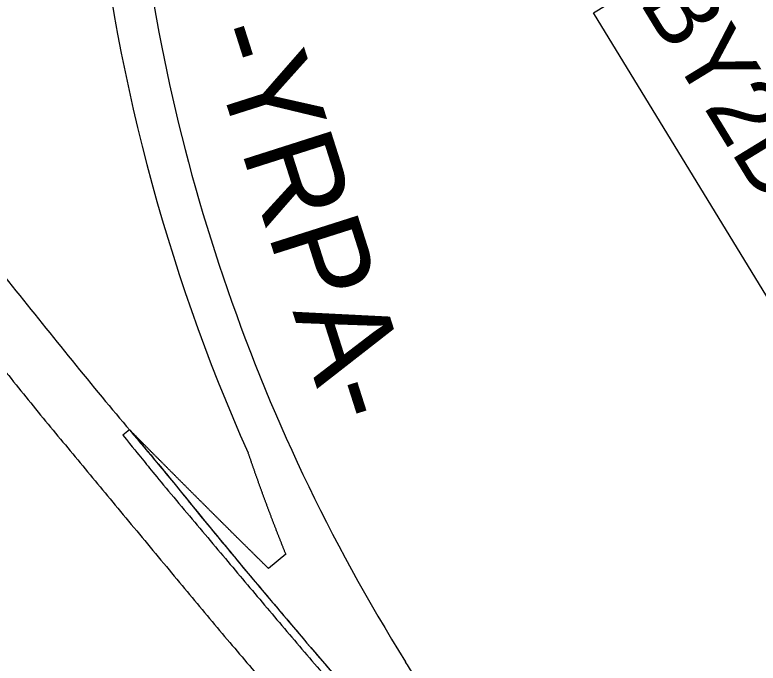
# Model space of a CAD drawing. Extents: x 1771071 to 1790027, y 804210 to 823391.
# Drawn here: x 1782402.5 to 1782802.4, y 812654.6 to 813003.3 of the extents above; entities that cross this region are included whole.
import ezdxf

# ---------------------------------------------------------------- set-up
doc = ezdxf.new("R2010")
doc.units = 0
for name, color, linetype in [('Default', 7, 'Continuous'), ('Exist Roads EOP', 7, 'Continuous'), ('Proposed Right of Way Monument PSD Text', 7, 'Continuous'), ('Scratch_Level_1', 7, 'Continuous'), ('Scratch_Level_7', 7, 'Continuous'), ('Scratch_Level_8', 7, 'Continuous')]:
    doc.layers.add(name, color=color, linetype=linetype)

msp = doc.modelspace()

# ---------------------------------------------------------------- linework, layer by layer
at = {"layer": 'Default'}
msp.add_lwpolyline([(1782786, 813048.4), (1782912.68, 812841.06), (1782840.57, 812797), (1782713.88, 813004.34)], close=True, dxfattribs=at)
at = {"layer": 'Exist Roads EOP'}
msp.add_spline([(1781123.7, 814794.56), (1781151.95, 814749.7), (1781175.35, 814711.94), (1781204.02, 814667.22), (1781230.05, 814626.42), (1781255.51, 814585.11), (1781282.93, 814541.39), (1781309.04, 814500.81), (1781338.07, 814453.82), (1781362.44, 814415.66), (1781389.1, 814373.22), (1781417.2, 814328.4), (1781443.82, 814286), (1781469.22, 814245.27), (1781496.33, 814201.88), (1781523.28, 814159.28), (1781551.49, 814114.9), (1781575, 814076.8), (1781602.27, 814034.47), (1781628.68, 813992.42), (1781657.71, 813946.44), (1781682.97, 813906.24), (1781710.54, 813862.11), (1781734.73, 813823.58), (1781763.09, 813779.24), (1781788.41, 813738.38), (1781814.81, 813696.35), (1781842.37, 813653.36), (1781868.91, 813610.68), (1781895.83, 813568.71), (1781924.39, 813523.58), (1781950.61, 813481.8), (1781976.68, 813442.67), (1782004.37, 813401.37), (1782031.99, 813360.12), (1782060.77, 813317.53), (1782089.19, 813276.64), (1782119.2, 813233.31), (1782146.2, 813195.67), (1782175.13, 813155.14), (1782204.07, 813115.4), (1782233.24, 813075.72), (1782263.79, 813034.43), (1782294.03, 812994.29), (1782325.04, 812953.86), (1782354.41, 812916.21), (1782385, 812877.38), (1782417.21, 812837.26), (1782449.43, 812797.65), (1782479.54, 812761.76), (1782513.17, 812720.66), (1782543.05, 812684.98), (1782576.35, 812645.89), (1782608.48, 812608.74), (1782640.69, 812571.37), (1782677.39, 812530.96), (1782710.34, 812494.65), (1782741.2, 812460.83), (1782775.54, 812424.09), (1782810.15, 812387.02), (1782844.36, 812350.73), (1782880.69, 812313.19), (1782914.85, 812277.64), (1782949.87, 812242.16), (1782985.13, 812206.92), (1783022.44, 812170.42), (1783054.86, 812138.57), (1783094.75, 812100.54), (1783130.02, 812066.91), (1783162.74, 812036.24), (1783200.85, 812001.49), (1783239.6, 811965.96), (1783275.52, 811933.35), (1783312.46, 811900.79)], degree=3, dxfattribs=at)
msp.add_open_spline([(1782044.92, 813285.25), (1782050.67, 813276.97), (1782056.46, 813268.71), (1782062.24, 813260.44), (1782072.54, 813245.71), (1782082.87, 813230.99), (1782093.24, 813216.29), (1782102.63, 813202.96), (1782112.08, 813189.67), (1782121.53, 813176.38), (1782130.68, 813163.53), (1782139.84, 813150.7), (1782149.05, 813137.9), (1782158.82, 813124.32), (1782168.64, 813110.78), (1782178.47, 813097.24), (1782188.39, 813083.57), (1782198.35, 813069.92), (1782208.33, 813056.29), (1782218.02, 813043.06), (1782227.8, 813029.89), (1782237.65, 813016.78), (1782248.53, 813002.3), (1782259.48, 812987.88), (1782270.47, 812973.49), (1782279.84, 812961.23), (1782289.23, 812948.99), (1782298.65, 812936.76), (1782309.31, 812922.92), (1782320.02, 812909.11), (1782330.76, 812895.33), (1782340.48, 812882.84), (1782350.26, 812870.4), (1782360.1, 812858.01), (1782370.44, 812844.98), (1782380.85, 812832.02), (1782391.28, 812819.08), (1782401.82, 812806), (1782412.32, 812792.9), (1782423.02, 812779.96), (1782433.65, 812767.11), (1782444.31, 812754.28), (1782454.97, 812741.45), (1782466.58, 812727.47), (1782478.2, 812713.49), (1782489.81, 812699.52), (1782500.55, 812686.61), (1782511.28, 812673.7), (1782522.16, 812660.91), (1782532.57, 812648.66), (1782543.09, 812636.51), (1782553.61, 812624.36), (1782564.93, 812611.27), (1782576.27, 812598.2), (1782587.59, 812585.12), (1782598.39, 812572.65), (1782609.08, 812560.09), (1782619.9, 812547.64), (1782629.97, 812536.06), (1782640.33, 812524.75), (1782650.68, 812513.41), (1782662.01, 812501), (1782673.39, 812488.63), (1782684.72, 812476.21), (1782696.75, 812463.02), (1782708.67, 812449.73), (1782720.73, 812436.57), (1782731.28, 812425.06), (1782741.93, 812413.64), (1782752.57, 812402.22), (1782763.95, 812390), (1782775.33, 812377.78), (1782786.79, 812365.63), (1782798.36, 812353.36), (1782809.99, 812341.16), (1782821.65, 812328.98), (1782834.08, 812316), (1782846.53, 812303.03), (1782859, 812290.07), (1782870.02, 812278.6), (1782880.99, 812267.09), (1782892.16, 812255.75), (1782903.38, 812244.37), (1782914.67, 812233.06), (1782925.94, 812221.72), (1782937.72, 812209.87), (1782949.5, 812198.01), (1782961.31, 812186.19), (1782973.07, 812174.42), (1782984.95, 812162.79), (1782996.81, 812151.13), (1783009.36, 812138.79), (1783021.93, 812126.45), (1783034.55, 812114.18), (1783046.41, 812102.66), (1783058.37, 812091.23), (1783070.34, 812079.83), (1783082.49, 812068.26), (1783094.66, 812056.71), (1783106.9, 812045.24), (1783119.62, 812033.34), (1783132.37, 812021.48), (1783145.13, 812009.62), (1783156.44, 811999.11), (1783167.76, 811988.6), (1783179.13, 811978.15), (1783191.42, 811966.86), (1783203.78, 811955.65), (1783216.13, 811944.44), (1783228.56, 811933.16), (1783241, 811921.89), (1783253.48, 811910.66), (1783266.09, 811899.3), (1783278.79, 811888.04), (1783291.5, 811876.8), (1783304.26, 811865.51), (1783317.04, 811854.25), (1783329.93, 811843.12), (1783341.92, 811832.75), (1783353.96, 811822.43), (1783366.03, 811812.15), (1783379.44, 811800.73), (1783392.86, 811789.32), (1783406.3, 811777.93), (1783419.39, 811766.84), (1783432.5, 811755.79), (1783445.62, 811744.73), (1783457.8, 811734.47), (1783469.97, 811724.21), (1783482.3, 811714.13), (1783494.7, 811704.01), (1783507.23, 811694.06), (1783519.67, 811683.97), (1783533.96, 811672.38), (1783548.22, 811660.73), (1783562.53, 811649.15), (1783574.14, 811639.75), (1783585.77, 811630.37), (1783597.48, 811621.1), (1783597.98, 811620.7), (1783598.49, 811620.3), (1783598.99, 811619.91)], degree=3, dxfattribs=at)
at = {"layer": 'Scratch_Level_1'}
msp.add_open_spline([(1782464.13, 812780.09), (1782469.29, 812774), (1782474.45, 812767.91), (1782479.54, 812761.76), (1782490.82, 812748.12), (1782501.87, 812734.28), (1782513.17, 812720.66), (1782523.08, 812708.72), (1782533.03, 812696.82), (1782543.05, 812684.98), (1782554.11, 812671.91), (1782565.17, 812658.85), (1782576.35, 812645.89), (1782587.05, 812633.5), (1782597.78, 812621.13), (1782608.48, 812608.74), (1782619.24, 812596.3), (1782629.7, 812583.6), (1782640.69, 812571.37), (1782652.85, 812557.83), (1782665.16, 812544.44), (1782677.39, 812530.96), (1782688.37, 812518.86), (1782699.35, 812506.75), (1782710.34, 812494.65), (1782720.59, 812483.35), (1782730.81, 812472.01), (1782741.2, 812460.83), (1782752.61, 812448.55), (1782764.1, 812436.35), (1782775.54, 812424.09), (1782787.08, 812411.74), (1782798.61, 812399.38), (1782810.15, 812387.02), (1782821.49, 812374.87), (1782832.87, 812362.74), (1782844.36, 812350.73), (1782856.4, 812338.15), (1782868.61, 812325.73), (1782880.69, 812313.19), (1782892.1, 812301.36), (1782903.41, 812289.44), (1782914.85, 812277.64), (1782926.42, 812265.71), (1782938.15, 812253.94), (1782949.87, 812242.16), (1782961.59, 812230.38), (1782973.28, 812218.57), (1782985.13, 812206.92), (1782988.2, 812203.91), (1782991.27, 812200.9), (1782994.34, 812197.89)], degree=3, dxfattribs=at)
at = {"layer": 'Scratch_Level_8'}
for p, q in [((1782464.15, 812780.15), (1782460.59, 812777.23)), ((1782548.19, 812713.18), (1782539.02, 812705.43))]:
    msp.add_line(p, q, dxfattribs=at)
for radius, end in [(1006, 204.03422), (984, 212.05563)]:
    msp.add_arc((1783446.7, 813177.51), radius, 185.30484, end, dxfattribs=at)
for points in [[(1782501.47, 812742.65), (1782500.96, 812743.15), (1782500.46, 812743.66), (1782499.95, 812744.16), (1782499.45, 812744.67), (1782498.94, 812745.17), (1782498.43, 812745.68), (1782497.93, 812746.18), (1782497.42, 812746.69), (1782496.92, 812747.2), (1782496.41, 812747.7), (1782495.91, 812748.21), (1782495.4, 812748.71), (1782494.9, 812749.22), (1782494.39, 812749.72), (1782493.89, 812750.23), (1782493.38, 812750.73), (1782492.87, 812751.24), (1782492.37, 812751.75), (1782491.86, 812752.25), (1782491.36, 812752.76), (1782490.85, 812753.26), (1782490.35, 812753.77), (1782489.84, 812754.27), (1782489.34, 812754.78), (1782488.83, 812755.29), (1782488.33, 812755.79), (1782487.82, 812756.3), (1782487.32, 812756.81), (1782486.82, 812757.31), (1782486.31, 812757.82), (1782485.81, 812758.32), (1782485.3, 812758.83), (1782484.8, 812759.34), (1782484.29, 812759.84), (1782483.79, 812760.35), (1782483.28, 812760.86), (1782482.78, 812761.36), (1782482.28, 812761.87), (1782481.77, 812762.38), (1782481.27, 812762.89), (1782480.76, 812763.39), (1782480.26, 812763.9), (1782479.75, 812764.41), (1782479.25, 812764.91), (1782478.75, 812765.42), (1782478.24, 812765.93), (1782477.74, 812766.44), (1782477.23, 812766.94), (1782476.73, 812767.45), (1782476.23, 812767.96), (1782475.72, 812768.46), (1782475.22, 812768.97), (1782474.72, 812769.48), (1782474.21, 812769.99), (1782473.71, 812770.5), (1782473.21, 812771), (1782472.7, 812771.51), (1782472.2, 812772.02), (1782471.69, 812772.53), (1782471.19, 812773.03), (1782470.69, 812773.54), (1782470.18, 812774.05), (1782469.68, 812774.56), (1782469.18, 812775.07), (1782468.68, 812775.58), (1782468.17, 812776.08), (1782467.67, 812776.59), (1782467.17, 812777.1), (1782466.66, 812777.61), (1782466.16, 812778.12), (1782465.66, 812778.63), (1782465.15, 812779.13), (1782464.15, 812780.15)], [(1782527.91, 812767.79), (1782528.42, 812766.3), (1782528.67, 812765.56), (1782528.93, 812764.81), (1782529.18, 812764.07), (1782529.44, 812763.33), (1782529.69, 812762.58), (1782529.95, 812761.84), (1782530.21, 812761.1), (1782530.46, 812760.36), (1782530.72, 812759.61), (1782530.98, 812758.87), (1782531.24, 812758.13), (1782531.5, 812757.39), (1782531.76, 812756.65), (1782532.02, 812755.91), (1782532.28, 812755.16), (1782532.55, 812754.42), (1782532.81, 812753.68), (1782533.07, 812752.94), (1782533.34, 812752.2), (1782533.6, 812751.46), (1782533.87, 812750.72), (1782534.13, 812749.98), (1782534.4, 812749.24), (1782534.67, 812748.5), (1782534.93, 812747.76), (1782535.2, 812747.02), (1782535.47, 812746.28), (1782535.74, 812745.54), (1782536.01, 812744.8), (1782536.28, 812744.06), (1782536.55, 812743.32), (1782536.82, 812742.59), (1782537.1, 812741.85), (1782537.37, 812741.11), (1782537.64, 812740.37), (1782537.92, 812739.63), (1782538.19, 812738.9), (1782538.47, 812738.16), (1782538.74, 812737.42), (1782539.02, 812736.68), (1782539.3, 812735.95), (1782539.58, 812735.21), (1782539.86, 812734.47), (1782540.13, 812733.73), (1782540.41, 812733), (1782540.69, 812732.26), (1782540.98, 812731.53), (1782541.26, 812730.79), (1782541.54, 812730.05), (1782541.82, 812729.32), (1782542.11, 812728.58), (1782542.39, 812727.85), (1782542.67, 812727.11), (1782542.96, 812726.38), (1782543.24, 812725.64), (1782543.53, 812724.91), (1782543.82, 812724.17), (1782544.1, 812723.44), (1782544.39, 812722.71), (1782544.68, 812721.97), (1782544.97, 812721.24), (1782545.26, 812720.5), (1782545.55, 812719.77), (1782545.84, 812719.04), (1782546.13, 812718.3), (1782546.43, 812717.57), (1782546.72, 812716.84), (1782547.01, 812716.11), (1782547.31, 812715.37), (1782547.6, 812714.64), (1782547.9, 812713.91), (1782548.19, 812713.18)], [(1782539.03, 812705.43), (1782538.52, 812705.93), (1782538.01, 812706.43), (1782537.5, 812706.93), (1782536.99, 812707.44), (1782536.48, 812707.94), (1782535.97, 812708.44), (1782535.46, 812708.94), (1782534.95, 812709.44), (1782534.45, 812709.94), (1782533.94, 812710.44), (1782533.43, 812710.95), (1782532.92, 812711.45), (1782532.41, 812711.95), (1782531.9, 812712.45), (1782531.39, 812712.95), (1782530.89, 812713.45), (1782530.38, 812713.96), (1782529.87, 812714.46), (1782529.36, 812714.96), (1782528.85, 812715.46), (1782528.34, 812715.96), (1782527.84, 812716.47), (1782527.33, 812716.97), (1782526.82, 812717.47), (1782526.31, 812717.97), (1782525.8, 812718.48), (1782525.3, 812718.98), (1782524.79, 812719.48), (1782524.28, 812719.98), (1782523.77, 812720.49), (1782523.26, 812720.99), (1782522.76, 812721.49), (1782522.25, 812721.99), (1782521.74, 812722.5), (1782521.23, 812723), (1782520.73, 812723.5), (1782520.22, 812724), (1782519.71, 812724.51), (1782519.2, 812725.01), (1782518.7, 812725.51), (1782518.19, 812726.02), (1782517.68, 812726.52), (1782517.17, 812727.02), (1782516.67, 812727.53), (1782516.16, 812728.03), (1782515.65, 812728.53), (1782515.15, 812729.04), (1782514.64, 812729.54), (1782514.13, 812730.04), (1782513.62, 812730.55), (1782513.12, 812731.05), (1782512.61, 812731.55), (1782512.1, 812732.06), (1782511.6, 812732.56), (1782511.09, 812733.07), (1782510.58, 812733.57), (1782510.08, 812734.07), (1782509.57, 812734.58), (1782509.06, 812735.08), (1782508.56, 812735.59), (1782508.05, 812736.09), (1782507.54, 812736.59), (1782507.04, 812737.1), (1782506.53, 812737.6), (1782506.02, 812738.11), (1782505.52, 812738.61), (1782505.01, 812739.12), (1782504.51, 812739.62), (1782504, 812740.13), (1782503.49, 812740.63), (1782502.99, 812741.13), (1782502.48, 812741.64), (1782501.98, 812742.14), (1782501.47, 812742.65)], [(1782794.93, 812420.34), (1782792.29, 812423.41), (1782789.65, 812426.49), (1782787.01, 812429.56), (1782784.37, 812432.64), (1782781.74, 812435.71), (1782779.1, 812438.79), (1782776.47, 812441.86), (1782773.84, 812444.94), (1782771.21, 812448.01), (1782768.58, 812451.09), (1782765.95, 812454.16), (1782763.33, 812457.24), (1782760.71, 812460.32), (1782758.09, 812463.4), (1782755.48, 812466.48), (1782752.86, 812469.56), (1782750.26, 812472.65), (1782747.65, 812475.73), (1782745.05, 812478.82), (1782742.45, 812481.91), (1782739.86, 812485), (1782737.27, 812488.1), (1782734.68, 812491.2), (1782732.1, 812494.3), (1782729.53, 812497.4), (1782726.95, 812500.5), (1782724.39, 812503.61), (1782721.83, 812506.72), (1782719.27, 812509.84), (1782716.72, 812512.96), (1782714.17, 812516.08), (1782711.64, 812519.2), (1782709.1, 812522.33), (1782706.58, 812525.46), (1782704.06, 812528.6), (1782701.54, 812531.74), (1782699.04, 812534.89), (1782696.54, 812538.04), (1782694.04, 812541.19), (1782691.56, 812544.35), (1782689.08, 812547.51), (1782686.61, 812550.68), (1782684.14, 812553.85), (1782681.69, 812557.03), (1782679.24, 812560.21), (1782676.81, 812563.4), (1782674.38, 812566.6), (1782671.95, 812569.8), (1782669.54, 812573), (1782667.14, 812576.21), (1782664.75, 812579.43), (1782662.36, 812582.65), (1782659.99, 812585.88), (1782657.62, 812589.12), (1782655.27, 812592.36), (1782652.93, 812595.61), (1782650.59, 812598.86), (1782648.27, 812602.12), (1782645.96, 812605.39), (1782643.66, 812608.67), (1782641.37, 812611.95), (1782639.09, 812615.24), (1782636.82, 812618.53), (1782634.57, 812621.83), (1782632.33, 812625.14), (1782630.1, 812628.46), (1782627.88, 812631.78), (1782625.67, 812635.11), (1782623.48, 812638.45), (1782621.3, 812641.8), (1782619.14, 812645.15), (1782616.99, 812648.52), (1782614.85, 812651.88), (1782612.71, 812655.29)]]:
    msp.add_spline(points, degree=3, dxfattribs=at)
msp.add_open_spline([(1782460.62, 812777.18), (1782466.02, 812770.54), (1782471.4, 812763.89), (1782476.83, 812757.28), (1782487.92, 812743.76), (1782499.25, 812730.44), (1782510.5, 812717.06), (1782521.03, 812704.55), (1782531.56, 812692.03), (1782542.13, 812679.55), (1782552.88, 812666.86), (1782563.68, 812654.22), (1782574.52, 812641.61), (1782585.44, 812628.92), (1782596.42, 812616.27), (1782607.41, 812603.63), (1782618.27, 812591.14), (1782629.14, 812578.66), (1782640.13, 812566.28), (1782650.79, 812554.26), (1782661.54, 812542.32), (1782672.31, 812530.39), (1782683.49, 812518), (1782694.68, 812505.62), (1782705.89, 812493.27), (1782717.37, 812480.63), (1782728.86, 812468.01), (1782740.44, 812455.48), (1782751.44, 812443.56), (1782762.5, 812431.7), (1782773.56, 812419.83), (1782785.14, 812407.4), (1782796.7, 812394.94), (1782808.38, 812382.59), (1782819.88, 812370.42), (1782831.47, 812358.35), (1782843.05, 812346.26), (1782854.09, 812334.73), (1782865.13, 812323.21), (1782876.19, 812311.7), (1782887.93, 812299.48), (1782899.69, 812287.27), (1782911.53, 812275.14), (1782923.1, 812263.3), (1782934.77, 812251.56), (1782946.42, 812239.79), (1782958.07, 812228.03), (1782969.67, 812216.23), (1782981.45, 812204.61), (1782984.74, 812201.36), (1782988.04, 812198.13), (1782991.34, 812194.9)], degree=3, dxfattribs=at)

# ---------------------------------------------------------------- texts
at = {"layer": 'Proposed Right of Way Monument PSD Text'}
msp.add_text('BY2D-50', height=37.325, rotation=301.4249, dxfattribs=at).set_placement((1782738.08, 813010.51))
at = {"layer": 'Scratch_Level_7'}
msp.add_text('-YRPA-', height=49.208, rotation=287.6825, dxfattribs=at).set_placement((1782504.03, 812993.57))

doc.saveas('drawing.dxf')
